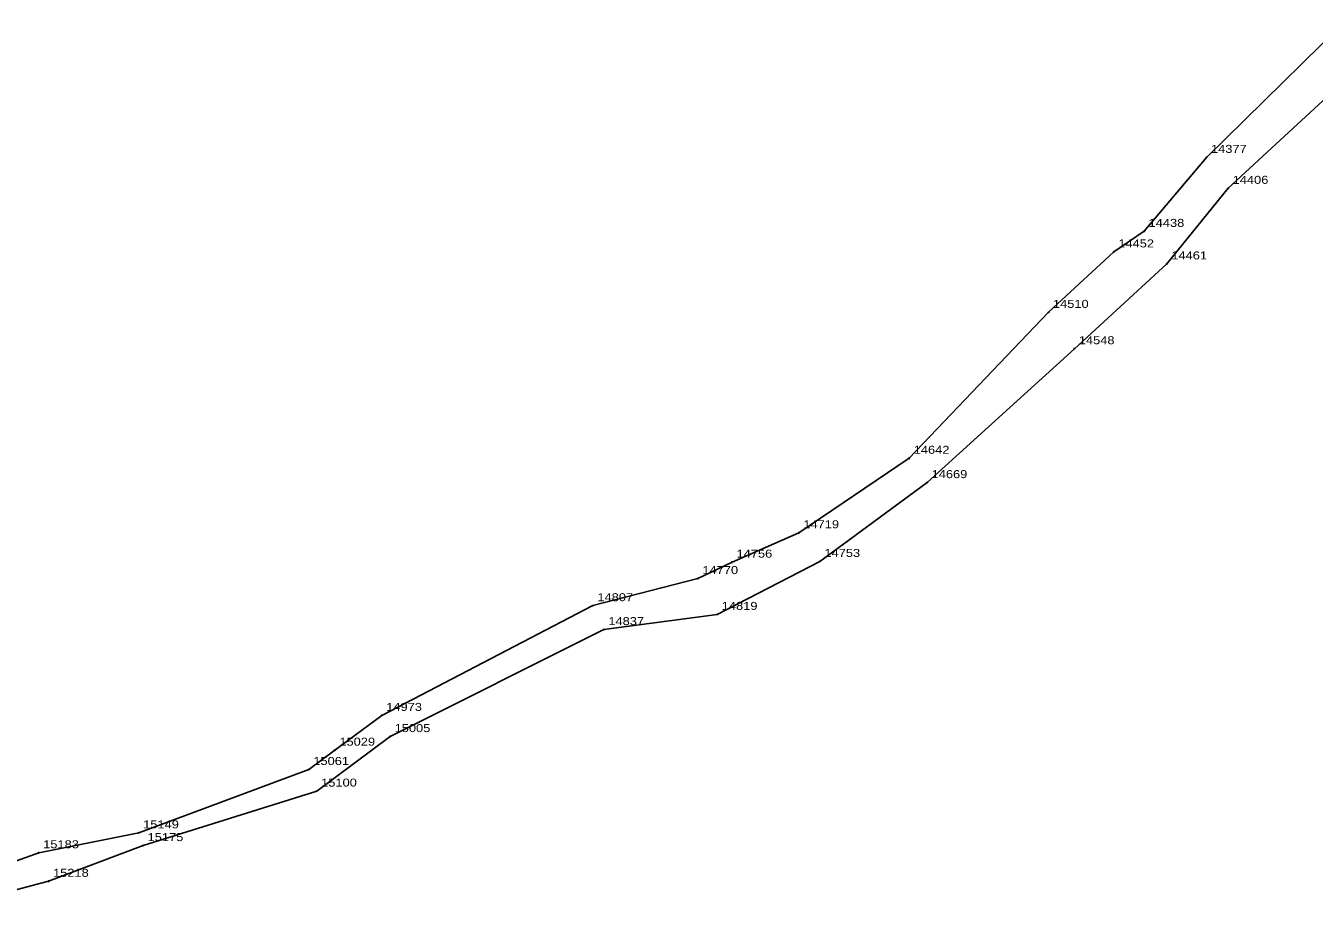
# Model space of a CAD drawing. Extents: x 4640203 to 4641683, y 5358965 to 5360242.
# Drawn here: x 4641393 to 4641537.8, y 5359791.7 to 5359891.7 of the extents above; entities that cross this region are included whole.
import ezdxf

# ---------------------------------------------------------------- set-up
doc = ezdxf.new("R2010")
doc.units = 0
doc.header["$LTSCALE"] = 0.36
for name, color, linetype, lineweight in [('25', 7, 'Continuous', 25), ('27', 7, 'Continuous', 25), ('8', 7, 'Continuous', 25)]:
    doc.layers.add(name, color=color, linetype=linetype, lineweight=lineweight)

msp = doc.modelspace()

# ---------------------------------------------------------------- linework, layer by layer
at = {"layer": '25'}
for points in [[(4641540.76, 5359891.69), (4641525.71, 5359876.89), (4641518.69, 5359868.57), (4641515.29, 5359866.26)], [(4641381.14, 5359791.65), (4641395.53, 5359795.47), (4641406.16, 5359799.49), (4641425.67, 5359805.62), (4641433.93, 5359811.75), (4641457.96, 5359823.78), (4641470.71, 5359825.49), (4641482.25, 5359831.45), (4641494.3, 5359840.31), (4641510.85, 5359855.37), (4641521.25, 5359864.91), (4641528.14, 5359873.41), (4641543.66, 5359887.74)], [(4641515.29, 5359866.26), (4641507.94, 5359859.46), (4641492.29, 5359843.05), (4641479.88, 5359834.67), (4641472.37, 5359831.37), (4641468.53, 5359829.52), (4641456.73, 5359826.47), (4641432.99, 5359814.13), (4641427.72, 5359810.22), (4641424.79, 5359808.05), (4641405.66, 5359800.92), (4641394.42, 5359798.68), (4641387.1, 5359796.04)]]:
    msp.add_lwpolyline(points, dxfattribs=at)
at = {"layer": '27'}
for points in [[(4641540.76, 5359891.69), (4641525.71, 5359876.89)], [(4641381.14, 5359791.65), (4641395.53, 5359795.47), (4641406.16, 5359799.49), (4641425.67, 5359805.62), (4641433.93, 5359811.75), (4641457.96, 5359823.78), (4641470.71, 5359825.49), (4641482.25, 5359831.45), (4641494.3, 5359840.31), (4641510.85, 5359855.37), (4641521.25, 5359864.91), (4641528.14, 5359873.41), (4641543.66, 5359887.74)], [(4641525.71, 5359876.89), (4641518.69, 5359868.57), (4641515.29, 5359866.26), (4641507.94, 5359859.46), (4641492.29, 5359843.05), (4641479.88, 5359834.67), (4641472.37, 5359831.37), (4641468.53, 5359829.52), (4641456.73, 5359826.47), (4641432.99, 5359814.13), (4641427.72, 5359810.22), (4641424.79, 5359808.05), (4641405.66, 5359800.92), (4641394.42, 5359798.68), (4641387.1, 5359796.04)]]:
    msp.add_lwpolyline(points, dxfattribs=at)
at = {"layer": '8'}
for centre in [(4641525.71, 5359876.89), (4641528.14, 5359873.41), (4641518.69, 5359868.57), (4641515.29, 5359866.26), (4641521.25, 5359864.91), (4641507.94, 5359859.46), (4641510.85, 5359855.37), (4641492.29, 5359843.05), (4641494.3, 5359840.31), (4641479.88, 5359834.67), (4641482.25, 5359831.45), (4641472.37, 5359831.37), (4641468.53, 5359829.52), (4641456.73, 5359826.47), (4641470.71, 5359825.49), (4641457.96, 5359823.78), (4641432.99, 5359814.13), (4641433.93, 5359811.75), (4641427.72, 5359810.22), (4641424.79, 5359808.05), (4641425.67, 5359805.62), (4641405.66, 5359800.92), (4641394.42, 5359798.68), (4641406.16, 5359799.49), (4641395.53, 5359795.47)]:
    msp.add_circle(centre, 0.045, dxfattribs=at)

# ---------------------------------------------------------------- texts
at = {"layer": '8', "width": 1.2}
for s, p in [('14377', (4641526.21, 5359877.39)), ('14406', (4641528.64, 5359873.91)), ('14438', (4641519.19, 5359869.07)), ('14452', (4641515.79, 5359866.76)), ('14461', (4641521.75, 5359865.41)), ('14510', (4641508.44, 5359859.96)), ('14548', (4641511.35, 5359855.87)), ('14642', (4641492.79, 5359843.55)), ('14669', (4641494.8, 5359840.81)), ('14719', (4641480.38, 5359835.17)), ('14756', (4641472.87, 5359831.87)), ('14753', (4641482.75, 5359831.95)), ('14770', (4641469.03, 5359830.02)), ('14807', (4641457.23, 5359826.97)), ('14819', (4641471.21, 5359825.99)), ('14837', (4641458.46, 5359824.28)), ('14973', (4641433.49, 5359814.63)), ('15005', (4641434.43, 5359812.25)), ('15029', (4641428.22, 5359810.72)), ('15061', (4641425.29, 5359808.55)), ('15100', (4641426.17, 5359806.12)), ('15149', (4641406.16, 5359801.42)), ('15183', (4641394.92, 5359799.18)), ('15175', (4641406.66, 5359799.99)), ('15218', (4641396.03, 5359795.97))]:
    msp.add_text(s, height=0.9, dxfattribs=at).set_placement(p)

doc.saveas('drawing.dxf')
